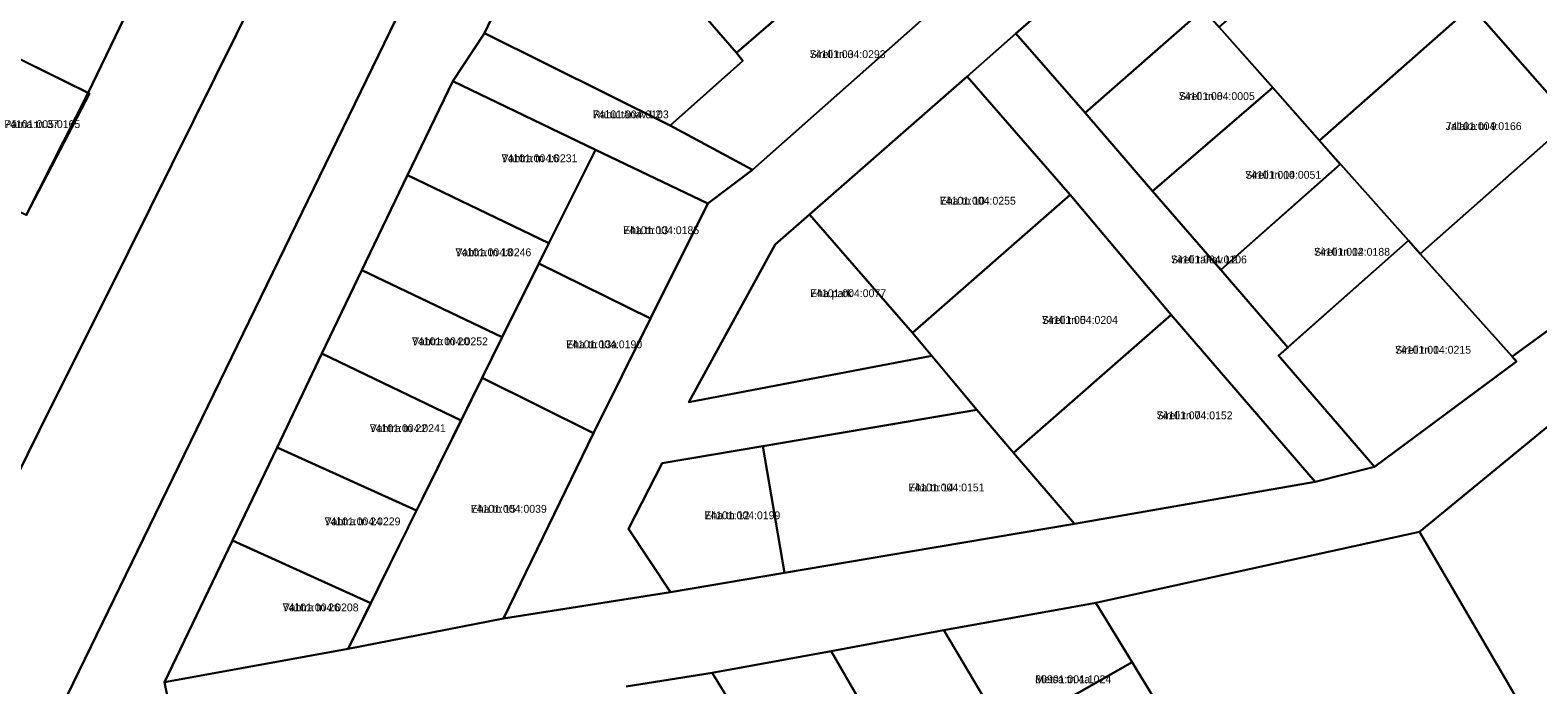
# Model space of a CAD drawing. Extents: x 524000 to 564260, y 6469338 to 6496391.
# Drawn here: x 537778.5 to 538066.5, y 6472932.3 to 6473057.4 of the extents above; entities that cross this region are included whole.
import ezdxf

# ---------------------------------------------------------------- set-up
doc = ezdxf.new("R2010")
doc.units = 0
for name, color, linetype in [('L_AADRESS', 7, 'Continuous'), ('PIIR', 7, 'Continuous'), ('TUNNUS', 7, 'Continuous')]:
    doc.layers.add(name, color=color, linetype=linetype)

msp = doc.modelspace()

# ---------------------------------------------------------------- linework, layer by layer
at = {"layer": 'PIIR'}
for points in [[(537956.46, 6473287.47), (537881.05, 6473130.21), (537883.27, 6473128.62), (537849.5, 6473061.8), (537774.4, 6472907.16)], [(537774.4, 6472907.16), (537849.5, 6473061.8), (537883.27, 6473128.62), (537881.05, 6473130.21), (537956.46, 6473287.47)], [(537974.33, 6473277.57), (537960.04, 6473247.79), (537938.83, 6473207.45), (537934.96, 6473198.12), (537916.45, 6473161.14), (537900.95, 6473129.73), (537895.98, 6473120.02), (537881.16, 6473090.1), (537865.31, 6473056.81), (537859.24, 6473047.61), (537850.59, 6473029.67), (537841.89, 6473011.54), (537834.25, 6472995.57), (537825.7, 6472977.65), (537817.2, 6472959.86), (537804.19, 6472932.78), (537806.63, 6472920.9)], [(537777.77, 6473022.03), (537789.59, 6473045.41), (537802.47, 6473072.14), (537807.87, 6473081.6), (537822.07, 6473109.06), (537837.99, 6473141.9), (537853.88, 6473174.7), (537864.09, 6473195.4), (537873.44, 6473214.34), (537886.07, 6473239.61), (537902.82, 6473273.77)], [(537758.2, 6472936.23), (537782.42, 6472985.19), (537790.56, 6473001.47), (537797.29, 6473015.04), (537826.2, 6473073.34), (537859.38, 6473140.3), (537883.17, 6473189.89), (537890.89, 6473205.72), (537899.34, 6473222.91), (537923.04, 6473270.09)], [(537923.04, 6473270.09), (537899.34, 6473222.91), (537890.89, 6473205.72), (537883.17, 6473189.89), (537859.38, 6473140.3), (537826.2, 6473073.34), (537797.29, 6473015.04), (537790.56, 6473001.47), (537782.42, 6472985.19), (537758.2, 6472936.23)], [(537806.63, 6472920.9), (537804.19, 6472932.78), (537839.27, 6472939.13), (537868.93, 6472944.94), (537900.85, 6472949.96), (537922.62, 6472953.66), (537946.68, 6472957.74), (537977.99, 6472963.06), (538023.97, 6472971.06), (538035.34, 6472973.95), (538062.44, 6472994.07), (538061.61, 6472995), (538092.79, 6473017.72), (538101.22, 6473023.61), (538133.75, 6473048.11), (538203.17, 6473097.43), (538229.44, 6473117.4), (538238.38, 6473124.26), (538280.97, 6473154.63)], [(538280.11, 6473132.45), (538239.83, 6473103.82), (538236.84, 6473108.34), (538198.52, 6473081.62), (538179.68, 6473067.6), (538163.25, 6473054.13), (538156.34, 6473048.5), (538096.61, 6473003.26), (538069.5, 6472982.51), (538043.92, 6472961.49), (537982.1, 6472947.96), (537977.91, 6472947.2), (537953.06, 6472942.7), (537931.53, 6472938.68), (537908.79, 6472934.6), (537892.39, 6472931.98)], [(537989.19, 6473076.36), (537966.8, 6473056.75), (537957.53, 6473048.55), (537927.42, 6473022.15), (537920.84, 6473016.4), (537904.32, 6472986.27), (537950.73, 6472995.13), (537959.34, 6472984.81), (537918.45, 6472977.87), (537899.26, 6472974.61), (537892.83, 6472962.06), (537900.85, 6472949.96), (537868.93, 6472944.94), (537886.16, 6472980.38), (537897.01, 6473002.26), (537907.98, 6473024.25), (537916.53, 6473030.7), (537948.73, 6473059.24)], [(537892.39, 6472931.98), (537908.79, 6472934.6), (537927.85, 6472903.53)]]:
    msp.add_lwpolyline(points, dxfattribs=at)
for points in [[(538023.36, 6473111.35), (538049.28, 6473081.9), (538067.02, 6473061.88), (538084.82, 6473041.79), (538101.22, 6473023.61), (538092.79, 6473017.72), (538072.92, 6473040.16), (538053.81, 6473061.92), (538034.77, 6473083.64), (538015.7, 6473105.17)], [(537865.31, 6473056.81), (537881.16, 6473090.1), (537901.21, 6473067.16), (537913.47, 6473053.06), (537914.66, 6473051.52), (537900.8, 6473039.14)], [(537901.21, 6473067.16), (537924.59, 6473087.22), (537936.86, 6473073.37), (537913.47, 6473053.06)], [(537765.37, 6473057.33), (537778.25, 6473084.07), (537802.47, 6473072.14), (537789.59, 6473045.41)], [(538024.81, 6473036.32), (538005.67, 6473057.95), (538034.77, 6473083.64), (538053.81, 6473061.92)], [(537966.8, 6473056.75), (537989.19, 6473076.36), (538002.62, 6473061.39), (537980.04, 6473041.61)], [(537948.73, 6473059.24), (537916.53, 6473030.7), (537900.8, 6473039.14), (537914.66, 6473051.52), (537913.47, 6473053.06), (537936.86, 6473073.37)], [(537980.04, 6473041.61), (538002.62, 6473061.39), (538005.67, 6473057.95), (538015.88, 6473046.41), (537992.93, 6473026.64)], [(538041.79, 6473017.16), (538024.81, 6473036.32), (538053.81, 6473061.92), (538072.92, 6473040.16), (538044.04, 6473014.64)], [(537757.32, 6473031.89), (537769.18, 6473055.47), (537789.88, 6473045.27), (537777.77, 6473022.03)], [(537865.31, 6473056.81), (537900.8, 6473039.14), (537916.53, 6473030.7), (537907.98, 6473024.25), (537886.51, 6473034.52), (537859.24, 6473047.61)], [(537966.8, 6473056.75), (537980.04, 6473041.61), (537992.93, 6473026.64), (538005.94, 6473011.55), (538018.73, 6472996.74), (538017, 6472995.21), (538033.05, 6472976.6), (538035.34, 6472973.95), (538023.97, 6472971.06), (537996.49, 6473002.99), (537977.18, 6473025.91), (537957.53, 6473048.55)], [(537859.24, 6473047.61), (537886.51, 6473034.52), (537877.62, 6473016.7), (537850.59, 6473029.67)], [(537927.42, 6473022.15), (537957.53, 6473048.55), (537977.18, 6473025.91), (537947.08, 6472999.51)], [(538005.94, 6473011.55), (537992.93, 6473026.64), (538015.88, 6473046.41), (538024.81, 6473036.32), (538028.77, 6473031.77)], [(538044.04, 6473014.64), (538072.92, 6473040.16), (538092.79, 6473017.72), (538061.61, 6472995)], [(537886.51, 6473034.52), (537907.98, 6473024.25), (537897.01, 6473002.26), (537875.67, 6473012.8)], [(538005.94, 6473011.55), (538028.81, 6473031.8), (538041.79, 6473017.16), (538018.73, 6472996.74)], [(537850.59, 6473029.67), (537877.62, 6473016.7), (537875.67, 6473012.8), (537868.67, 6472998.68), (537841.89, 6473011.54)], [(537959.34, 6472984.81), (537947.08, 6472999.51), (537977.18, 6473025.91), (537996.49, 6473002.99), (537966.39, 6472976.59)], [(537927.42, 6473022.15), (537947.08, 6472999.51), (537950.73, 6472995.13), (537904.32, 6472986.27), (537920.84, 6473016.4)], [(538017, 6472995.21), (538041.79, 6473017.16), (538044.04, 6473014.64), (538061.61, 6472995), (538062.44, 6472994.07), (538035.34, 6472973.95), (538033.05, 6472976.6)], [(537841.89, 6473011.54), (537868.67, 6472998.68), (537864.84, 6472990.91), (537860.84, 6472982.81), (537834.25, 6472995.57)], [(537875.67, 6473012.8), (537897.01, 6473002.26), (537886.16, 6472980.38), (537864.84, 6472990.91), (537868.67, 6472998.68)], [(538023.97, 6472971.06), (537977.99, 6472963.06), (537966.39, 6472976.59), (537996.49, 6473002.99)], [(537834.25, 6472995.57), (537860.84, 6472982.81), (537852.33, 6472965.57), (537825.7, 6472977.65)], [(537839.27, 6472939.13), (537864.84, 6472990.91), (537886.16, 6472980.38), (537868.93, 6472944.94)], [(537918.45, 6472977.87), (537942.52, 6472981.96), (537959.34, 6472984.81), (537966.39, 6472976.59), (537977.99, 6472963.06), (537946.68, 6472957.74), (537922.62, 6472953.66)], [(538063.82, 6472927.37), (538043.92, 6472961.49), (538069.5, 6472982.51), (538197.42, 6472785.22), (538167.63, 6472787.73), (538094.14, 6472794.44), (538052.97, 6472797.96), (538053.69, 6472807.94), (538096.61, 6472807.14), (538101.49, 6472803.54), (538148.19, 6472799.6), (538143.82, 6472806.23), (538125.46, 6472834.03), (538102.73, 6472867.87), (538080.43, 6472860.92), (538075.66, 6472867.92), (538096.35, 6472877.38), (538076.89, 6472907.52)], [(537825.7, 6472977.65), (537852.33, 6472965.57), (537850.81, 6472962.53), (537843.59, 6472947.88), (537817.2, 6472959.86)], [(537892.83, 6472962.06), (537899.26, 6472974.61), (537918.45, 6472977.87), (537922.62, 6472953.66), (537900.85, 6472949.96)], [(537817.2, 6472959.86), (537843.59, 6472947.88), (537839.27, 6472939.13), (537804.19, 6472932.78)], [(538022.72, 6472881.08), (538014.96, 6472893.88), (537997.23, 6472923.11), (537982.1, 6472947.96), (538043.92, 6472961.49), (538063.82, 6472927.37), (538037.41, 6472912.57), (538047.97, 6472897.18)], [(537968.23, 6472917.21), (537953.06, 6472942.7), (537977.91, 6472947.2), (537982.1, 6472947.96), (537989.01, 6472936.61), (537986.38, 6472935.11), (537968.34, 6472924.82), (537971.65, 6472919.27)], [(537950.29, 6472906.18), (537931.53, 6472938.68), (537953.06, 6472942.7), (537968.23, 6472917.21), (537971.31, 6472912.04)], [(537927.85, 6472903.53), (537908.79, 6472934.6), (537931.53, 6472938.68), (537950.29, 6472906.18), (537933.05, 6472901.44)], [(537993.74, 6472921.12), (537972.96, 6472909.24), (537971.31, 6472912.04), (537968.23, 6472917.21), (537971.65, 6472919.27), (537968.34, 6472924.82), (537986.38, 6472935.11), (537989.01, 6472936.61), (537997.23, 6472923.11)]]:
    msp.add_lwpolyline(points, close=True, dxfattribs=at)

# ---------------------------------------------------------------- texts
at = {"layer": 'L_AADRESS'}
for s, p in [('Sireli tn 3', (537927.43, 6473052.04)), ('Sireli tn 8', (537997.94, 6473044.02)), ('Rahu tänav L2', (537886, 6473040.53)), ('Pärna tn 37', (537773.6, 6473038.67)), ('Jalaka tn 9', (538048.91, 6473038.28)), ('Vahtra tn 16', (537868.56, 6473032.15)), ('Sireli tn 10', (538010.63, 6473028.98)), ('Eha tn 10', (537952.3, 6473024.03)), ('Eha tn 13', (537891.82, 6473018.4)), ('Vahtra tn 18', (537859.76, 6473014.18)), ('Sireli tänav L2', (537996.44, 6473012.81)), ('Sireli tn 12', (538023.77, 6473014.27)), ('Eha park', (537927.52, 6473006.36)), ('Sireli tn 5', (537971.79, 6473001.25)), ('Vahtra tn 20', (537851.47, 6472997.17)), ('Eha tn 13a', (537880.93, 6472996.59)), ('Sireli tn 14', (538039.25, 6472995.55)), ('Sireli tn 7', (537993.7, 6472983.02)), ('Vahtra tn 22', (537843.41, 6472980.57)), ('Eha tn 14', (537946.32, 6472969.24)), ('Eha tn 15', (537862.71, 6472965.16)), ('Eha tn 12', (537907.32, 6472963.92)), ('Vahtra tn 24', (537834.76, 6472962.76)), ('Vahtra tn 26', (537826.76, 6472946.32)), ('Metsa tn 4a', (537970.52, 6472932.59))]:
    msp.add_text(s, height=1.5, dxfattribs=at).set_placement(p)
at = {"layer": 'TUNNUS'}
for s, p in [('74101:004:0293', (537927.43, 6473052.04)), ('74101:004:0005', (537997.94, 6473044.02)), ('74101:004:0103', (537886, 6473040.53)), ('74101:005:0165', (537773.6, 6473038.67)), ('74101:004:0166', (538048.91, 6473038.28)), ('74101:004:0231', (537868.56, 6473032.15)), ('74101:004:0051', (538010.63, 6473028.98)), ('74101:004:0255', (537952.3, 6473024.03)), ('74101:004:0185', (537891.82, 6473018.4)), ('74101:004:0246', (537859.76, 6473014.18)), ('74101:004:0188', (538023.77, 6473014.27)), ('74101:004:0106', (537996.44, 6473012.81)), ('74101:004:0077', (537927.52, 6473006.36)), ('74101:004:0204', (537971.79, 6473001.25)), ('74101:004:0252', (537851.47, 6472997.17)), ('74101:004:0190', (537880.93, 6472996.59)), ('74101:004:0215', (538039.25, 6472995.55)), ('74101:004:0152', (537993.7, 6472983.02)), ('74101:004:0241', (537843.41, 6472980.57)), ('74101:004:0151', (537946.32, 6472969.24)), ('74101:004:0039', (537862.71, 6472965.16)), ('74101:004:0199', (537907.32, 6472963.92)), ('74101:004:0229', (537834.76, 6472962.76)), ('74101:004:0208', (537826.76, 6472946.32)), ('80901:001:1024', (537970.52, 6472932.59))]:
    msp.add_text(s, height=1.5, dxfattribs=at).set_placement(p)

doc.saveas('drawing.dxf')
